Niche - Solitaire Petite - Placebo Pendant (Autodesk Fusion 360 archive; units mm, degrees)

design "Globe - Modular" references "Modular - Placebo - Bayonet Connector", "Modular - Placedo - Cord Set"
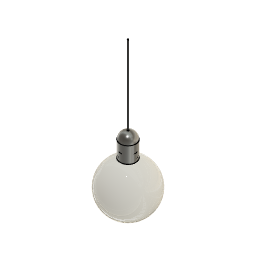
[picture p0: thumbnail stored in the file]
sketch "Sketch1" plane through (0, 0, 0) normal (0, 1, 0) x axis (1, 0, 0)
  line L1 (-26.924, -104.0655) -> (-26.924, -91.3655)
  line L2 (26.924, -104.0655) -> (26.924, -91.3655)
  line L3 (-25.019, -104.0655) -> (-25.019, -89.9296)
  line L4 (25.019, -104.0655) -> (25.019, -89.9296)
  line L5 (-25.019, -104.0655) -> (-26.924, -104.0655)
  line L6 (26.924, -104.0655) -> (25.019, -104.0655)
  line L7 (0, 101.6) -> (0, -114.3)
  arc A1 centre (0, 0) radius 95.25 clockwise from (-26.924, -91.3655) to (26.924, -91.3655)
  arc A2 centre (0, 0) radius 93.345 clockwise from (-25.019, -89.9296) to (25.019, -89.9296)
  point P1 (0, 0)
  point P2 (0, 0)
  coincident P1 P2
  collinear L5 L6
  vertical L7
  dimension "d1" diameter A1 = 190.5
  dimension "d5" distance L1 L2 = 53.848
revolve "Revolve1" sketch "Sketch1" AlongAngle 360 bodies "Solitaire Pettie Modular"
component_from_bodies "Body->Comp"
component_insert "Component Insert1"
component_insert "Component Insert2"
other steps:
base_feature "Base Feature" bodies "Solitaire Pettie Modular"
create_component "CreateComponent1"
remove_body "RemoveBody1"
named bodies: "Solitaire Pettie Modular"

design "Modular - Placebo - Bayonet Connector"
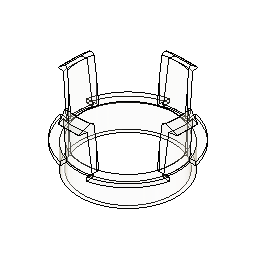
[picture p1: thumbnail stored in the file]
sketch "Sketch1" plane through (0, 0, 0) normal (0, 0, 1) x axis (1, 0, 0)
  circle C1 centre (0, 0) radius 23.241
  point P1 (0, 0)
  point P2 (0, 0)
  coincident P1 P2
  dimension "d1" diameter C1 = 46.482
extrude "Extrude1" new body sketch "Sketch1" along normal blind 11.176
sketch "Sketch2" plane through (0, 0, 11.176) normal (0, 0, 1) x axis (-1, 0, 0)
  line L1 (-23.2795, -6.35) -> (-26.1645, -6.35)
  line L2 (-23.2795, 6.35) -> (-26.1645, 6.35)
  line L3 (26.1645, -6.35) -> (23.2795, -6.35)
  line L4 (26.1645, 6.35) -> (23.2795, 6.35)
  line L5 (6.35, -23.2795) -> (6.35, -26.1645)
  line L6 (-6.35, -23.2795) -> (-6.35, -26.1645)
  line L7 (6.35, 26.1645) -> (6.35, 23.2795)
  line L8 (-6.35, 26.1645) -> (-6.35, 23.2795)
  line L9 (0, -24.13) -> (0, -26.924)
  line L10 (6.35, -23.2795) -> (6.35, -22.3567)
  line L11 (-6.35, -23.2795) -> (-6.35, -22.3567)
  line L12 (23.2795, -6.35) -> (22.3567, -6.35)
  line L13 (23.2795, 6.35) -> (22.3567, 6.35)
  line L14 (-23.2795, 6.35) -> (-22.3567, 6.35)
  line L15 (-23.2795, -6.35) -> (-22.3567, -6.35)
  line L16 (6.35, 22.3567) -> (6.35, 23.2795)
  line L17 (-6.35, 22.3567) -> (-6.35, 23.2795)
  circle C1 centre (0, 0) radius 23.241
  arc A1 centre (0, 0) radius 26.924 clockwise from (-6.35, -26.1645) to (-26.1645, -6.35)
  arc A2 centre (0, 0) radius 26.924 clockwise from (26.1645, -6.35) to (6.35, -26.1645)
  arc A3 centre (0, 0) radius 24.13 clockwise from (23.2795, 6.35) to (23.2795, -6.35)
  arc A4 centre (0, 0) radius 24.13 clockwise from (6.35, -23.2795) to (-6.35, -23.2795)
  arc A5 centre (0, 0) radius 26.924 clockwise from (6.35, 26.1645) to (26.1645, 6.35)
  arc A6 centre (0, 0) radius 26.924 clockwise from (-26.1645, 6.35) to (-6.35, 26.1645)
  arc A7 centre (0, 0) radius 24.13 clockwise from (-6.35, 23.2795) to (6.35, 23.2795)
  arc A8 centre (0, 0) radius 24.13 clockwise from (-23.2795, -6.35) to (-23.2795, 6.35)
  point P2 (0, 0)
  point P4 (0, 0)
  point P12 (-23.2795, -6.35)
  point P13 (-22.3567, -6.35)
  point P14 (-23.2795, 6.35)
  point P15 (-22.3567, 6.35)
  point P16 (22.3567, -6.35)
  point P18 (22.3567, 6.35)
  point P24 (6.35, 23.2795)
  point P28 (6.35, -22.3567)
  point P29 (-6.35, -22.3567)
  point P31 (-6.35, 26.1645)
  point P35 (0, -24.13)
  point P36 (6.35, 22.3567)
  point P37 (-6.35, 22.3567)
  coincident P2 P4
  vertical L9
  concentric A2 A3
  concentric A1 A2
  coincident P12 A3
  coincident C1 P13
  coincident P14 A3
  coincident C1 P15
  coincident C1 P16
  coincident C1 P18
  concentric A2 A5
  coincident P24 L5
  concentric A3 A7
  concentric A4 A7
  coincident C1 P28
  coincident C1 P29
  coincident P31 A5
  concentric A5 A6
  concentric A7 A8
  coincident A4 P35
  horizontal L12
  coincident C1 P36
  parallel L7 L16
  coincident C1 P37
  parallel L8 L17
  dimension "d4" diameter A2 = 53.848
extrude "Extrude2" add sketch "Sketch2" profile of C1 A8 L10 L11 L12 L13 L14 L15 L16 L17 along normal blind 0.762
extrude "Extrude3" add sketch "Sketch2" profile of C1 A6 L7 L8 L4 L3 L10 L11 L12 L13 L14 L15 L16 L17 along normal blind 1.7018
extrude "Extrude4" add sketch "Sketch2" profile of C1 along normal blind 1.7018
work_plane "WorkPlane1" AlongDistance 33.8963
sketch "Sketch3" plane through (0, 0, 33.8963) normal (0, 0, 1) x axis (1, 0, 0)
  line L1 (0, 20.3925) -> (0, 27.5045)
  line L2 (-6.604, 20.3925) -> (-6.604, 27.5045)
  line L3 (6.604, 20.3925) -> (6.604, 27.5045)
  circle C1 centre (0, 0) radius 23.7363
  circle C2 centre (0, 0) radius 27.305
  arc A1 centre (0.0021, 0.2001) radius 23.9364 clockwise from (-6.604, 23.2068) to (6.604, 23.208)
  arc A2 centre (0.0021, 0.2001) radius 21.3964 clockwise from (-6.604, 20.5511) to (6.604, 20.5525)
  point P1 (0, 0)
  point P2 (0, 0)
  point P6 (-6.604, 27.5045)
  point P8 (6.604, 27.5045)
  point P7 (-6.604, 20.3925)
  point P9 (6.604, 20.3925)
  point P11 (-6.604, 23.2068)
  point P12 (6.604, 23.208)
  point P14 (-6.604, 20.5511)
  point P15 (6.604, 20.5525)
  coincident P1 P2
  concentric C1 C2
  vertical L1
  symmetric L1 P6 P8
  symmetric L1 P7 P9
  tangent C1 A1
  coincident L2 P11
  coincident L3 P12
  concentric A1 A2
  coincident L2 P14
  coincident L3 P15
  dimension "d14" diameter C1 = 47.4726
  dimension "d15" diameter C2 = 54.61
  dimension "d16" = 6.604
extrude "Extrude5" new body sketch "Sketch3" profile of C1 L1 L2 L3 A1 A2 against normal blind 21.59
sketch "Sketch4" plane through (0, 0, 33.8963) normal (0, 0, 1) x axis (-1, 0, 0)
  line L1 (6.604, -20.5511) -> (6.604, -23.2068)
  line L2 (-6.604, -23.208) -> (-6.604, -20.5525)
  line L3 (-5.08, -26.67) -> (-6.604, -20.5525)
  line L4 (5.08, -26.67) -> (-5.08, -26.67)
  line L5 (6.604, -20.5511) -> (5.08, -26.67)
  arc A1 centre (-0.0021, -0.2001) radius 23.9364 clockwise from (6.604, -23.2068) to (-6.604, -23.208)
  arc A2 centre (-0.0021, -0.2001) radius 21.3964 clockwise from (6.604, -20.5511) to (-6.604, -20.5525)
  point P6 (-6.604, -20.5525)
  point P7 (-6.604, -20.5525)
  point P5 (6.604, -20.5511)
  point P10 (6.604, -20.5511)
  coincident P6 P7
  perpendicular L2 L4
  coincident P5 P10
extrude "Extrude6" add sketch "Sketch4" profile of A1 A2 L3 L4 L5 against normal blind 3.175
move "Move1"
sketch "Sketch5" plane through (0, 3.4565, 35.8974) normal (0, 0.0958, 0.9954) x axis (-1, 0, 0)
  line L1 (6.604, -19.277) -> (6.604, -21.9327)
  line L2 (-6.604, -21.9339) -> (-6.604, -19.2784)
  line L3 (-5.08, -25.3959) -> (-5.8947, -22.1257)
  line L4 (5.08, -25.3959) -> (-5.08, -25.3959)
  line L5 (5.8948, -22.1246) -> (5.08, -25.3959)
  line L6 (-8.1218, -17.3223) -> (-6.0831, -25.506)
  line L7 (-0.004, -17.3223) -> (-0.0002, -17.3223)
  line L8 (-8.1218, -17.3223) -> (-6.8295, -17.3223)
  line L9 (0, -25.3959) -> (0.0001, -20.3223)
  line L10 (-6.8295, -17.3223) -> (-4.7917, -25.5025)
  line L11 (8.1222, -17.3227) -> (6.0831, -25.5062)
  line L12 (8.1222, -17.3227) -> (6.8299, -17.3226)
  line L13 (-4.7917, -25.5025) -> (-6.1096, -25.506)
  line L14 (4.7917, -25.5027) -> (6.0831, -25.5062)
  line L15 (6.8299, -17.3226) -> (4.7917, -25.5027)
  arc A1 centre (-0.0021, 1.074) radius 23.9364 clockwise from (6.604, -21.9327) to (5.8948, -22.1246)
  arc A2 centre (-0.0021, 1.074) radius 21.3964 clockwise from (6.604, -19.277) to (-6.604, -19.2784)
  arc A3 centre (-0.0021, 1.074) radius 23.9364 clockwise from (-5.8947, -22.1257) to (-6.604, -21.9339)
  arc A4 centre (-0.0021, 1.074) radius 18.3964 clockwise from (5.6778, -16.4236) to (-5.6783, -16.4247)
  point P14 (-0.0002, -17.3223)
  point P15 (-8.1218, -17.3223)
  point P16 (-0.004, -17.3223)
  point P17 (0.0001, -20.3223)
  point P18 (0, -25.3959)
  point P20 (8.1222, -17.3227)
  point P19 (-6.8295, -17.3223)
  point P21 (6.8299, -17.3226)
  point P23 (-6.0831, -25.506)
  point P26 (6.8299, -17.3226)
  point P24 (-4.7917, -25.5025)
  point P25 (4.7917, -25.5027)
  midpoint A4 P14
  horizontal L7
  coincident P15 L7
  coincident A4 P16
  collinear L7 L8
  midpoint A2 P17
  midpoint L4 P18
  symmetric P15 L9 P20
  symmetric L9 P19 P21
  coincident L13 P23
  symmetric L9 P19 P26
  symmetric L9 P24 P25
  dimension "d22" = -3
extrude "Extrude7" cut sketch "Sketch5" profile of A1 L1 A2 L2 A3 L3 L4 L5 L8 L6 L10 L11 L12 L13 L14 L15 against normal blind 25.146 taper -1.45
remove_body "RemoveBody1"
remove_body "RemoveBody2"
chamfer "Chamfer1" sketch "Sketch4" distance 4.572 distance 3.048
circular_pattern "C-Pattern1" TotalAngle 360
extrude "Extrude8" add sketch "Sketch4" along a picked direction blind 0.508
extrude "Extrude9" add of existing geometry blind 0.508
extrude "Extrude10" add of existing geometry blind 0.508
extrude "Extrude11" add of existing geometry blind 0.508
hole "Hole1" sketch "Sketch4" HoleDepth 38.1 HoleDiameter 42.926 TipAngle 118
fillet "Fillet1" sketch "Sketch4" radius 1.27

design "Modular - Placedo - Cord Set"
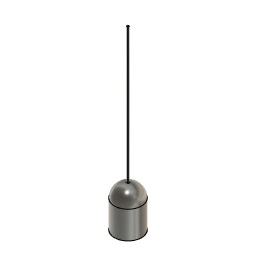
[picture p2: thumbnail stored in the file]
sketch "Sketch1" plane through (0, 0, 0) normal (0, 1, 0) x axis (1, 0, 0)
  line L1 (0, -88.9) -> (0, 0)
  line L2 (-29.5402, -88.9) -> (-29.5402, 0)
  line L3 (29.5402, -88.9) -> (29.5402, 0)
  line L4 (29.5402, 8.5598) -> (29.5402, -59.3598)
  line L5 (-29.5402, -59.3598) -> (-29.5402, 8.5598)
  line L6 (0, 38.1) -> (0, -88.9)
  line L7 (29.5402, 0) -> (-29.5402, 0)
  arc A1 centre (0, 8.5598) radius 29.5402 clockwise from (-29.5402, 8.5598) to (29.5402, 8.5598)
  arc A2 centre (0, -59.3598) radius 29.5402 clockwise from (29.5402, -59.3598) to (-29.5402, -59.3598)
  point P1 (0, 0)
  point P2 (0, 0)
  point P4 (-29.5402, 0)
  point P6 (29.5402, 0)
  point P5 (-29.5402, -88.9)
  point P7 (29.5402, -88.9)
  point P3 (0, -88.9)
  point P14 (0, 38.1)
  coincident P1 P2
  vertical L1
  symmetric L1 P4 P6
  symmetric L1 P5 P7
  tangent L4 A1
  tangent A1 L5
  parallel L4 L5
  tangent L5 A2
  tangent L4 A2
  midpoint P3 A2
  midpoint A1 P14
  parallel L1 L6
  dimension "d1" = 29.5402
revolve "Revolve1" sketch "Sketch1" AlongAngle 360
shell "Shell1" innerThickness 1.524
sketch "Sketch2" plane through (0, 0, 0) normal (0, 0, 1) x axis (1, 0, 0)
  circle C1 centre (0, 0) radius 2.8575
  point P1 (0, 0)
  point P2 (0, 0)
  coincident P1 P2
  dimension "d4" diameter C1 = 5.715
extrude "Extrude1" cut sketch "Sketch2" along normal blind 101.6
sketch "Sketch3" plane through (0, 0, 0) normal (0, 0, 1) x axis (1, 0, 0)
  circle C1 centre (0, 0) radius 2.286
  point P1 (0, 0)
  point P2 (0, 0)
  coincident P1 P2
  dimension "d7" diameter C1 = 4.572
extrude "Extrude2" new body sketch "Sketch3" along normal blind 304.8
move "Move1"
sketch "Sketch4" plane through (0, 0, 0) normal (0, 0, 1) x axis (1, 0, 0)
  circle C1 centre (0, 0) radius 18.796
  point P1 (0, 0)
  point P2 (0, 0)
  coincident P1 P2
  dimension "d10" diameter C1 = 37.592
extrude "Extrude3" new body sketch "Sketch4" along normal blind 31.75
move "Move2"
offset_faces "OffsetFaces1" distance 38.1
